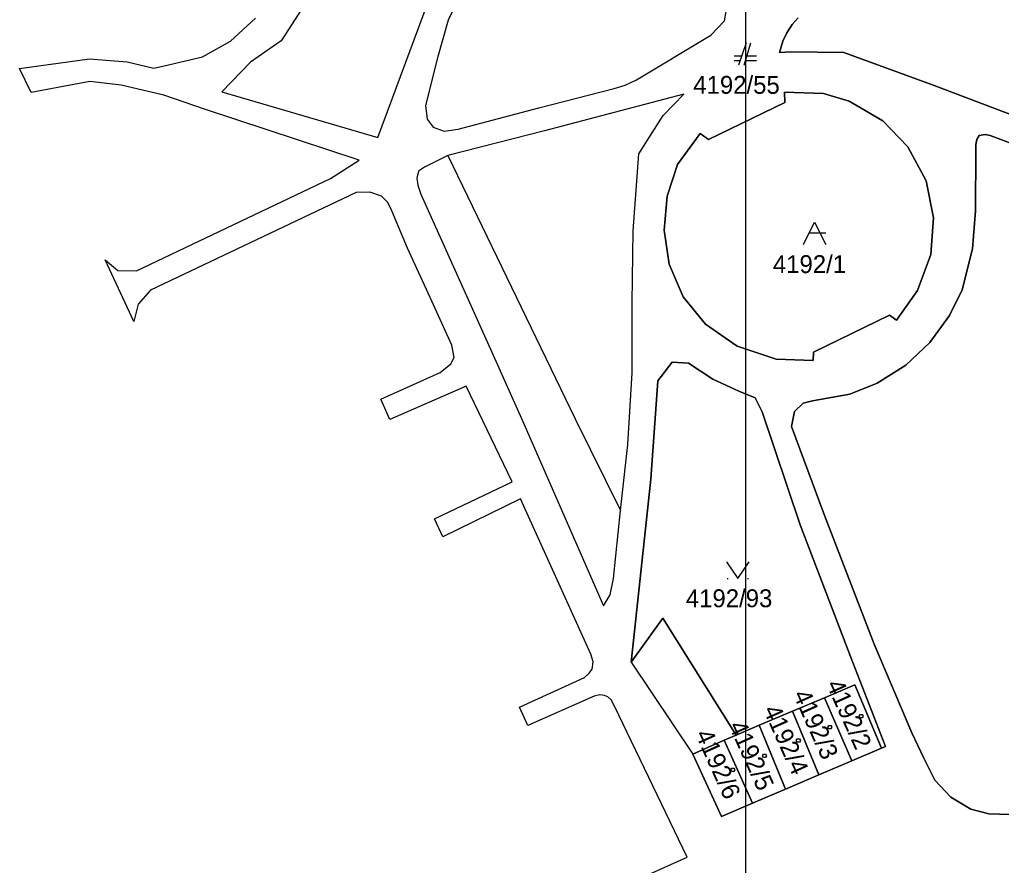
# Model space of a CAD drawing. Extents: x -263587 to -261993, y -1238795 to -1236748.
# Drawn here: x -263057 to -262969.2, y -1237791.2 to -1237715.5 of the extents above; entities that cross this region are included whole.
import ezdxf

# ---------------------------------------------------------------- set-up
doc = ezdxf.new("R2010")
doc.units = 0
doc.layers.add('Vrstva 1', color=7, linetype='Continuous')
doc.layers.add('Vrstva 51', color=7, linetype='Continuous')

msp = doc.modelspace()

# ---------------------------------------------------------------- linework, layer by layer
at = {"layer": 'Vrstva 1'}
for p, q in [((-263030.39, -1237712.43), (-263033.58, -1237717.41)), ((-263024.93, -1237726.07), (-263020.41, -1237713.88)), ((-263017.79, -1237713.75), (-263018.66, -1237715.58)), ((-263038.1, -1237717.46), (-263035.87, -1237715.4)), ((-263018.66, -1237715.58), (-263019.62, -1237718.95)), ((-262995.15, -1237716.92), (-262993.94, -1237715.62)), ((-262993.94, -1237715.62), (-262993.78, -1237714.79)), ((-262987.35, -1237715.35), (-262987.88, -1237715.97)), ((-262987.88, -1237715.97), (-262987.35, -1237715.35)), ((-262987.88, -1237715.97), (-262988.37, -1237716.71)), ((-262988.37, -1237716.71), (-262987.88, -1237715.97)), ((-263001.8, -1237720.92), (-262995.15, -1237716.92)), ((-262988.37, -1237716.71), (-262988.72, -1237717.45)), ((-262988.72, -1237717.45), (-262988.37, -1237716.71)), ((-263040.63, -1237718.86), (-263038.1, -1237717.46)), ((-263033.58, -1237717.41), (-263036.32, -1237719.34)), ((-262991.99, -1237717.59), (-262992.69, -1237719.59)), ((-262992.19, -1237719.59), (-262991.59, -1237717.59)), ((-262988.72, -1237717.45), (-262989.02, -1237718.48)), ((-262989.02, -1237718.48), (-262988.72, -1237717.45)), ((-263056.97, -1237719.9), (-263050.71, -1237719.04)), ((-263050.71, -1237719.04), (-263047.36, -1237719.31)), ((-263044.04, -1237719.66), (-263040.63, -1237718.86)), ((-263019.62, -1237718.95), (-263020.69, -1237723.2)), ((-262992.41, -1237718.79), (-262993.09, -1237718.79)), ((-262991.09, -1237718.79), (-262991.95, -1237718.79)), ((-262989.02, -1237718.48), (-262988.02, -1237718.42)), ((-262988.02, -1237718.42), (-262989.02, -1237718.48)), ((-262988.02, -1237718.42), (-262983.28, -1237718.47)), ((-262983.28, -1237718.47), (-262988.02, -1237718.42)), ((-262983.28, -1237718.47), (-262975.19, -1237721.42)), ((-262975.19, -1237721.42), (-262983.28, -1237718.47)), ((-263055.95, -1237722.03), (-263056.97, -1237719.9)), ((-263047.36, -1237719.31), (-263044.97, -1237719.88)), ((-263044.97, -1237719.88), (-263044.04, -1237719.66)), ((-263036.32, -1237719.34), (-263038.88, -1237721.97)), ((-262993.09, -1237719.19), (-262992.55, -1237719.19)), ((-262992.07, -1237719.19), (-262991.09, -1237719.19)), ((-263050.68, -1237721.05), (-263055.95, -1237722.03)), ((-263047.9, -1237721.38), (-263050.68, -1237721.05)), ((-263044.09, -1237722.29), (-263047.9, -1237721.38)), ((-263010.54, -1237723.41), (-263003.82, -1237721.68)), ((-263003.82, -1237721.68), (-263002.82, -1237721.39)), ((-263002.82, -1237721.39), (-263001.8, -1237720.92)), ((-262975.19, -1237721.42), (-262963.05, -1237726.05)), ((-262963.05, -1237726.05), (-262975.19, -1237721.42)), ((-263040.34, -1237723.58), (-263044.09, -1237722.29)), ((-263038.88, -1237721.97), (-263024.93, -1237726.07)), ((-262997.59, -1237722.18), (-263010.05, -1237725.48)), ((-262999.43, -1237724.1), (-262997.59, -1237722.18)), ((-262988.57, -1237722.01), (-262988.55, -1237722.94)), ((-262985.08, -1237722.12), (-262988.57, -1237722.01)), ((-262988.55, -1237722.94), (-262988.57, -1237722.01)), ((-262988.57, -1237722.01), (-262985.08, -1237722.12)), ((-262982.79, -1237722.83), (-262985.08, -1237722.12)), ((-262985.08, -1237722.12), (-262982.79, -1237722.83)), ((-263020.69, -1237723.2), (-263020.54, -1237724.44)), ((-263017.76, -1237725.33), (-263010.54, -1237723.41)), ((-262988.55, -1237722.94), (-262995.36, -1237726.25)), ((-262995.36, -1237726.25), (-262988.55, -1237722.94)), ((-262979.79, -1237724.57), (-262982.79, -1237722.83)), ((-262982.79, -1237722.83), (-262979.79, -1237724.57)), ((-263026.62, -1237728.11), (-263040.34, -1237723.58)), ((-263001.6, -1237727.54), (-262999.43, -1237724.1)), ((-263020.54, -1237724.44), (-263020, -1237725.16)), ((-263020, -1237725.16), (-263019.01, -1237725.5)), ((-262977.54, -1237726.89), (-262979.79, -1237724.57)), ((-262979.79, -1237724.57), (-262977.54, -1237726.89)), ((-263019.01, -1237725.5), (-263017.76, -1237725.33)), ((-263010.05, -1237725.48), (-263018.67, -1237727.68)), ((-262996.11, -1237725.7), (-262998.15, -1237728.48)), ((-262998.15, -1237728.48), (-262996.11, -1237725.7)), ((-262995.36, -1237726.25), (-262996.11, -1237725.7)), ((-262996.11, -1237725.7), (-262995.36, -1237726.25)), ((-262971.17, -1237725.89), (-262971.38, -1237726.24)), ((-262971.38, -1237726.24), (-262971.17, -1237725.89)), ((-262970.64, -1237725.79), (-262971.17, -1237725.89)), ((-262971.17, -1237725.89), (-262970.64, -1237725.79)), ((-262970.2, -1237725.9), (-262970.64, -1237725.79)), ((-262970.64, -1237725.79), (-262970.2, -1237725.9)), ((-262962.05, -1237728.94), (-262970.2, -1237725.9)), ((-262970.2, -1237725.9), (-262962.05, -1237728.94)), ((-262975.92, -1237729.95), (-262977.54, -1237726.89)), ((-262977.54, -1237726.89), (-262975.92, -1237729.95)), ((-262971.38, -1237726.24), (-262971.47, -1237726.71)), ((-262971.47, -1237726.71), (-262971.38, -1237726.24)), ((-262971.47, -1237726.71), (-262971.46, -1237727.2)), ((-262971.46, -1237727.2), (-262971.47, -1237726.71)), ((-263018.67, -1237727.68), (-263020.77, -1237728.72)), ((-263018.67, -1237727.68), (-263007.3, -1237751.25)), ((-263002.11, -1237734.42), (-263001.6, -1237727.54)), ((-262971.46, -1237727.2), (-262971.51, -1237732.63)), ((-262971.51, -1237732.63), (-262971.46, -1237727.2)), ((-263029.17, -1237729.75), (-263026.62, -1237728.11)), ((-263020.77, -1237728.72), (-263021.29, -1237729.09)), ((-262998.15, -1237728.48), (-262999.08, -1237731.33)), ((-262999.08, -1237731.33), (-262998.15, -1237728.48)), ((-263021.29, -1237729.09), (-263021.45, -1237729.72)), ((-263046.52, -1237738), (-263029.17, -1237729.75)), ((-263021.45, -1237729.72), (-263021.36, -1237730.32)), ((-263021.36, -1237730.32), (-263021.1, -1237731.15)), ((-262975.24, -1237733.25), (-262975.92, -1237729.95)), ((-262975.92, -1237729.95), (-262975.24, -1237733.25)), ((-263026.89, -1237730.99), (-263045.26, -1237739.73)), ((-263025.66, -1237730.95), (-263026.89, -1237730.99)), ((-263024.6, -1237731.33), (-263025.66, -1237730.95)), ((-263024.05, -1237731.88), (-263024.6, -1237731.33)), ((-263021.1, -1237731.15), (-263014.76, -1237745.27)), ((-262999.08, -1237731.33), (-262999.33, -1237734.36)), ((-262999.33, -1237734.36), (-262999.08, -1237731.33)), ((-263023.68, -1237732.64), (-263024.05, -1237731.88)), ((-263022.29, -1237735.98), (-263023.68, -1237732.64)), ((-262971.51, -1237732.63), (-262971.77, -1237736.03)), ((-262971.77, -1237736.03), (-262971.51, -1237732.63)), ((-262975.48, -1237736.54), (-262975.24, -1237733.25)), ((-262975.24, -1237733.25), (-262975.48, -1237736.54)), ((-263002.2, -1237740.86), (-263002.11, -1237734.42)), ((-262999.33, -1237734.36), (-262998.89, -1237737.4)), ((-262998.89, -1237737.4), (-262999.33, -1237734.36)), ((-262984.88, -1237734.63), (-262986.38, -1237734.63)), ((-263020.27, -1237740.39), (-263022.29, -1237735.98)), ((-262976.67, -1237739.77), (-262975.48, -1237736.54)), ((-262975.48, -1237736.54), (-262976.67, -1237739.77)), ((-262971.77, -1237736.03), (-262972.7, -1237739.7)), ((-262972.7, -1237739.7), (-262971.77, -1237736.03)), ((-263046.77, -1237742.52), (-263049.32, -1237737.02)), ((-263049.32, -1237737.02), (-263048.19, -1237737.98)), ((-262998.89, -1237737.4), (-262997.64, -1237740.32)), ((-262997.64, -1237740.32), (-262998.89, -1237737.4)), ((-263048.19, -1237737.98), (-263046.52, -1237738)), ((-263045.26, -1237739.73), (-263046.37, -1237740.97)), ((-262978.57, -1237742.41), (-262976.67, -1237739.77)), ((-262976.67, -1237739.77), (-262978.57, -1237742.41)), ((-262972.7, -1237739.7), (-262973.81, -1237741.98)), ((-262973.81, -1237741.98), (-262972.7, -1237739.7)), ((-263046.37, -1237740.97), (-263046.77, -1237742.52)), ((-263018.33, -1237744.66), (-263020.27, -1237740.39)), ((-263002.19, -1237747.12), (-263002.2, -1237740.86)), ((-262997.64, -1237740.32), (-262995.64, -1237742.76)), ((-262995.64, -1237742.76), (-262997.64, -1237740.32)), ((-262985.98, -1237745.28), (-262979.19, -1237741.95)), ((-262979.19, -1237741.95), (-262985.98, -1237745.28)), ((-262979.19, -1237741.95), (-262978.57, -1237742.41)), ((-262978.57, -1237742.41), (-262979.19, -1237741.95)), ((-262995.64, -1237742.76), (-262992.82, -1237744.75)), ((-262992.82, -1237744.75), (-262995.64, -1237742.76)), ((-262973.81, -1237741.98), (-262975.59, -1237744.42)), ((-262975.59, -1237744.42), (-262973.81, -1237741.98)), ((-262975.59, -1237744.42), (-262977.74, -1237746.45)), ((-262977.74, -1237746.45), (-262975.59, -1237744.42)), ((-263018.12, -1237745.75), (-263018.33, -1237744.66)), ((-263014.76, -1237745.27), (-263011.96, -1237751.48)), ((-262992.82, -1237744.75), (-262989.31, -1237745.91)), ((-262989.31, -1237745.91), (-262992.82, -1237744.75)), ((-262986.01, -1237746.03), (-262985.98, -1237745.28)), ((-262985.98, -1237745.28), (-262986.01, -1237746.03)), ((-263019.36, -1237747.1), (-263018.42, -1237746.33)), ((-263018.42, -1237746.33), (-263018.12, -1237745.75)), ((-262999.9, -1237747.83), (-262998.62, -1237746.17)), ((-262998.62, -1237746.17), (-262999.9, -1237747.83)), ((-262998.62, -1237746.17), (-262997.15, -1237746.26)), ((-262997.15, -1237746.26), (-262998.62, -1237746.17)), ((-262997.15, -1237746.26), (-262994.98, -1237747.7)), ((-262994.98, -1237747.7), (-262997.15, -1237746.26)), ((-262989.31, -1237745.91), (-262986.01, -1237746.03)), ((-262986.01, -1237746.03), (-262989.31, -1237745.91)), ((-263024.66, -1237749.48), (-263019.36, -1237747.1)), ((-263002.59, -1237753.52), (-263002.19, -1237747.12)), ((-262977.74, -1237746.45), (-262980.28, -1237748.04)), ((-262980.28, -1237748.04), (-262977.74, -1237746.45)), ((-263000.52, -1237756.63), (-262999.9, -1237747.83)), ((-262999.9, -1237747.83), (-263000.52, -1237756.63)), ((-262994.98, -1237747.7), (-262992.67, -1237748.75)), ((-262992.67, -1237748.75), (-262994.98, -1237747.7)), ((-262980.28, -1237748.04), (-262982.74, -1237749.02)), ((-262982.74, -1237749.02), (-262980.28, -1237748.04)), ((-263017.05, -1237748.32), (-263023.86, -1237751.29)), ((-263012.92, -1237756.87), (-263017.05, -1237748.32)), ((-262992.67, -1237748.75), (-262991.2, -1237749.36)), ((-262991.2, -1237749.36), (-262992.67, -1237748.75)), ((-263023.86, -1237751.29), (-263024.66, -1237749.48)), ((-262991.2, -1237749.36), (-262990.56, -1237750.6)), ((-262990.56, -1237750.6), (-262991.2, -1237749.36)), ((-262986.92, -1237749.84), (-262987.69, -1237750.59)), ((-262987.69, -1237750.59), (-262986.92, -1237749.84)), ((-262986.07, -1237749.63), (-262986.92, -1237749.84)), ((-262986.92, -1237749.84), (-262986.07, -1237749.63)), ((-262982.74, -1237749.02), (-262986.07, -1237749.63)), ((-262986.07, -1237749.63), (-262982.74, -1237749.02)), ((-262990.56, -1237750.6), (-262987.18, -1237760.72)), ((-262987.18, -1237760.72), (-262990.56, -1237750.6)), ((-262987.69, -1237750.59), (-262987.94, -1237751.91)), ((-262987.94, -1237751.91), (-262987.69, -1237750.59)), ((-263011.96, -1237751.48), (-263004.76, -1237767.98)), ((-263007.3, -1237751.25), (-263003.23, -1237759.43)), ((-262987.94, -1237751.91), (-262985.02, -1237759.8)), ((-262985.02, -1237759.8), (-262987.94, -1237751.91)), ((-263003.23, -1237759.43), (-263002.59, -1237753.52)), ((-263019.86, -1237760.17), (-263012.92, -1237756.87)), ((-263002.28, -1237773), (-263000.52, -1237756.63)), ((-263000.52, -1237756.63), (-263002.28, -1237773)), ((-263012.19, -1237758.39), (-263019.13, -1237761.78)), ((-263005.89, -1237772.28), (-263012.19, -1237758.39)), ((-263003.86, -1237765.53), (-263003.23, -1237759.43)), ((-263019.13, -1237761.78), (-263019.86, -1237760.17)), ((-262985.02, -1237759.8), (-262980.56, -1237771.41)), ((-262980.56, -1237771.41), (-262985.02, -1237759.8)), ((-262987.18, -1237760.72), (-262982.68, -1237772.49)), ((-262982.68, -1237772.49), (-262987.18, -1237760.72)), ((-263004.17, -1237766.98), (-263003.86, -1237765.53)), ((-262993.7, -1237765.52), (-262993.6, -1237765.52)), ((-262991.9, -1237765.52), (-262991.8, -1237765.52)), ((-263004.76, -1237767.98), (-263004.17, -1237766.98)), ((-262999.46, -1237769.07), (-263002.28, -1237773)), ((-263002.28, -1237773), (-262999.46, -1237769.07)), ((-262992.91, -1237779.53), (-262999.46, -1237769.07)), ((-262999.46, -1237769.07), (-262992.91, -1237779.53)), ((-262980.56, -1237771.41), (-262977.2, -1237779.32)), ((-262977.2, -1237779.32), (-262980.56, -1237771.41)), ((-263005.69, -1237772.99), (-263005.89, -1237772.28)), ((-262982.68, -1237772.49), (-262979.55, -1237780.55)), ((-262979.55, -1237780.55), (-262982.68, -1237772.49)), ((-263005.79, -1237773.62), (-263005.69, -1237772.99)), ((-263002.28, -1237773), (-262996.77, -1237781.23)), ((-263012.26, -1237777.04), (-263006.47, -1237774.38)), ((-263006.47, -1237774.38), (-263006.04, -1237774)), ((-263006.04, -1237774), (-263005.79, -1237773.62)), ((-262985.01, -1237776.19), (-262982.28, -1237775.04)), ((-262982.28, -1237775.04), (-262985.01, -1237776.19)), ((-262982.28, -1237775.04), (-262979.9, -1237780.7)), ((-262979.9, -1237780.7), (-262982.28, -1237775.04)), ((-263005.59, -1237776.05), (-263011.53, -1237778.67)), ((-263005.08, -1237775.94), (-263005.59, -1237776.05)), ((-263004.68, -1237775.98), (-263005.08, -1237775.94)), ((-263004.37, -1237776.12), (-263004.68, -1237775.98)), ((-263004.09, -1237776.37), (-263004.37, -1237776.12)), ((-262987.85, -1237777.39), (-262985.01, -1237776.19)), ((-262985.01, -1237776.19), (-262987.85, -1237777.39)), ((-262985.01, -1237776.19), (-262982.56, -1237781.84)), ((-262982.56, -1237781.84), (-262985.01, -1237776.19)), ((-263011.53, -1237778.67), (-263012.26, -1237777.04)), ((-263003.77, -1237776.93), (-263004.09, -1237776.37)), ((-262997.27, -1237790.45), (-263003.77, -1237776.93)), ((-262990.85, -1237778.65), (-262987.85, -1237777.39)), ((-262987.85, -1237777.39), (-262990.85, -1237778.65)), ((-262987.85, -1237777.39), (-262985.51, -1237783.09)), ((-262985.51, -1237783.09), (-262987.85, -1237777.39)), ((-262992.91, -1237779.53), (-262990.85, -1237778.65)), ((-262990.85, -1237778.65), (-262992.91, -1237779.53)), ((-262990.85, -1237778.65), (-262988.5, -1237784.37)), ((-262988.5, -1237784.37), (-262990.85, -1237778.65)), ((-262993.97, -1237779.98), (-262992.91, -1237779.53)), ((-262992.91, -1237779.53), (-262993.97, -1237779.98)), ((-262977.2, -1237779.32), (-262976.12, -1237781.6)), ((-262976.12, -1237781.6), (-262977.2, -1237779.32)), ((-262996.77, -1237781.23), (-262993.97, -1237779.98)), ((-262993.97, -1237779.98), (-262996.77, -1237781.23)), ((-262991.44, -1237785.63), (-262993.97, -1237779.98)), ((-262993.97, -1237779.98), (-262991.44, -1237785.63)), ((-262979.55, -1237780.55), (-262979.9, -1237780.7)), ((-262979.9, -1237780.7), (-262979.55, -1237780.55)), ((-262994.21, -1237786.81), (-262996.77, -1237781.23)), ((-262996.77, -1237781.23), (-262994.21, -1237786.81)), ((-262979.9, -1237780.7), (-262982.56, -1237781.84)), ((-262982.56, -1237781.84), (-262979.9, -1237780.7)), ((-262982.56, -1237781.84), (-262985.51, -1237783.09)), ((-262985.51, -1237783.09), (-262982.56, -1237781.84)), ((-262976.12, -1237781.6), (-262975.13, -1237783.56)), ((-262975.13, -1237783.56), (-262976.12, -1237781.6)), ((-262985.51, -1237783.09), (-262988.5, -1237784.37)), ((-262988.5, -1237784.37), (-262985.51, -1237783.09)), ((-262975.13, -1237783.56), (-262973.71, -1237785.09)), ((-262973.71, -1237785.09), (-262975.13, -1237783.56)), ((-262988.5, -1237784.37), (-262991.44, -1237785.63)), ((-262991.44, -1237785.63), (-262988.5, -1237784.37)), ((-262991.44, -1237785.63), (-262994.21, -1237786.81)), ((-262994.21, -1237786.81), (-262991.44, -1237785.63)), ((-262973.71, -1237785.09), (-262971.93, -1237786.16)), ((-262971.93, -1237786.16), (-262973.71, -1237785.09)), ((-262971.93, -1237786.16), (-262970.32, -1237786.58)), ((-262970.32, -1237786.58), (-262971.93, -1237786.16)), ((-262970.32, -1237786.58), (-262968.41, -1237786.64)), ((-262968.41, -1237786.64), (-262970.32, -1237786.58)), ((-263004.76, -1237793.79), (-262997.27, -1237790.45))]:
    msp.add_line(p, q, dxfattribs=at)
for points in [[(-262986.88, -1237735.63), (-262985.88, -1237733.63), (-262984.88, -1237735.63)], [(-262993.75, -1237764.02), (-262992.75, -1237765.52), (-262991.75, -1237764.02)]]:
    msp.add_lwpolyline(points, dxfattribs=at)
for points in [[(-262981.63, -1237777.7), (-262981.54, -1237777.85), (-262981.63, -1237778), (-262981.81, -1237778), (-262981.9, -1237777.85), (-262981.81, -1237777.7)], [(-262984.43, -1237778.68), (-262984.34, -1237778.83), (-262984.43, -1237778.98), (-262984.61, -1237778.98), (-262984.7, -1237778.83), (-262984.61, -1237778.68)], [(-262987.25, -1237779.85), (-262987.16, -1237780), (-262987.25, -1237780.15), (-262987.43, -1237780.15), (-262987.52, -1237780), (-262987.43, -1237779.85)], [(-262990.27, -1237781.23), (-262990.18, -1237781.38), (-262990.27, -1237781.53), (-262990.45, -1237781.53), (-262990.54, -1237781.38), (-262990.45, -1237781.23)], [(-262993.12, -1237782.48), (-262993.03, -1237782.63), (-262993.12, -1237782.78), (-262993.3, -1237782.78), (-262993.39, -1237782.63), (-262993.3, -1237782.48)]]:
    msp.add_lwpolyline(points, close=True, dxfattribs=at)
at = {"layer": 'Vrstva 51'}
msp.add_lwpolyline([(-262992.03, -1237088.09), (-262695.03, -1237088.09), (-262695.03, -1238768.09), (-262992.03, -1238768.09)], close=True, dxfattribs=at)

# ---------------------------------------------------------------- texts
at = {"layer": 'Vrstva 1'}
for s, p in [('4192/55', (-262996.734, -1237722.16)), ('4192/1', (-262989.617, -1237738.2)), ('4192/93', (-262997.4, -1237768.09))]:
    msp.add_text(s, height=1.6, dxfattribs=at).set_placement(p)
for s, p in [('4192/2', (-262984.87, -1237774.99)), ('4192/3', (-262987.84, -1237775.9)), ('4192/4', (-262990.51, -1237777.27)), ('4192/5', (-262993.59, -1237778.68)), ('4192/6', (-262996.578, -1237779.45))]:
    msp.add_text(s, height=1.6, rotation=294.15653, dxfattribs=at).set_placement(p)

doc.saveas('drawing.dxf')
